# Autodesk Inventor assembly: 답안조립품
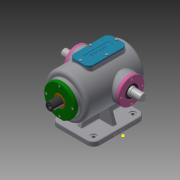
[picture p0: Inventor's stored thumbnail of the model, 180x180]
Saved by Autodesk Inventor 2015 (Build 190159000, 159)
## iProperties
Created: 2021-11
Part Number: 답안조립품
Document SubType Name: Assembly
Designer: now
Author: now
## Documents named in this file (14)
- C:\Users\now\Desktop\711106V1014\답안조립품.iam
- C:\Users\now\Desktop\711106V1014\베어링 6205.ipt
- 베어링 6205.ipt
- C:\Users\now\Desktop\711106V1014\본체.ipt
- C:\Users\now\Desktop\711106V1014\볼트 M4x0.7.ipt
- C:\Users\now\Desktop\711106V1014\부시.ipt
- C:\Users\now\Desktop\711106V1014\상부커버.ipt
- C:\Users\now\Desktop\711106V1014\슬라이드 커버.ipt
- C:\Users\now\Desktop\711106V1014\슬라이드.ipt
- C:\Users\now\Desktop\711106V1014\오일실.ipt
- 오일실.ipt
- C:\Users\now\Desktop\711106V1014\육각머리볼트 M4.ipt
- C:\Users\now\Desktop\711106V1014\축 커버.ipt
- C:\Users\now\Desktop\711106V1014\편심축.ipt
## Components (12 placed, 1 different names)
1. M4x0.7:9
2. M4x0.7:10
3. M4x0.7:11
4. M4x0.7:12
5. M4x0.7:1
6. M4x0.7:3
7. M4x0.7:4
8. M4x0.7:5
9. M4x0.7:2
10. M4x0.7:6
11. M4x0.7:7
12. M4x0.7:8
